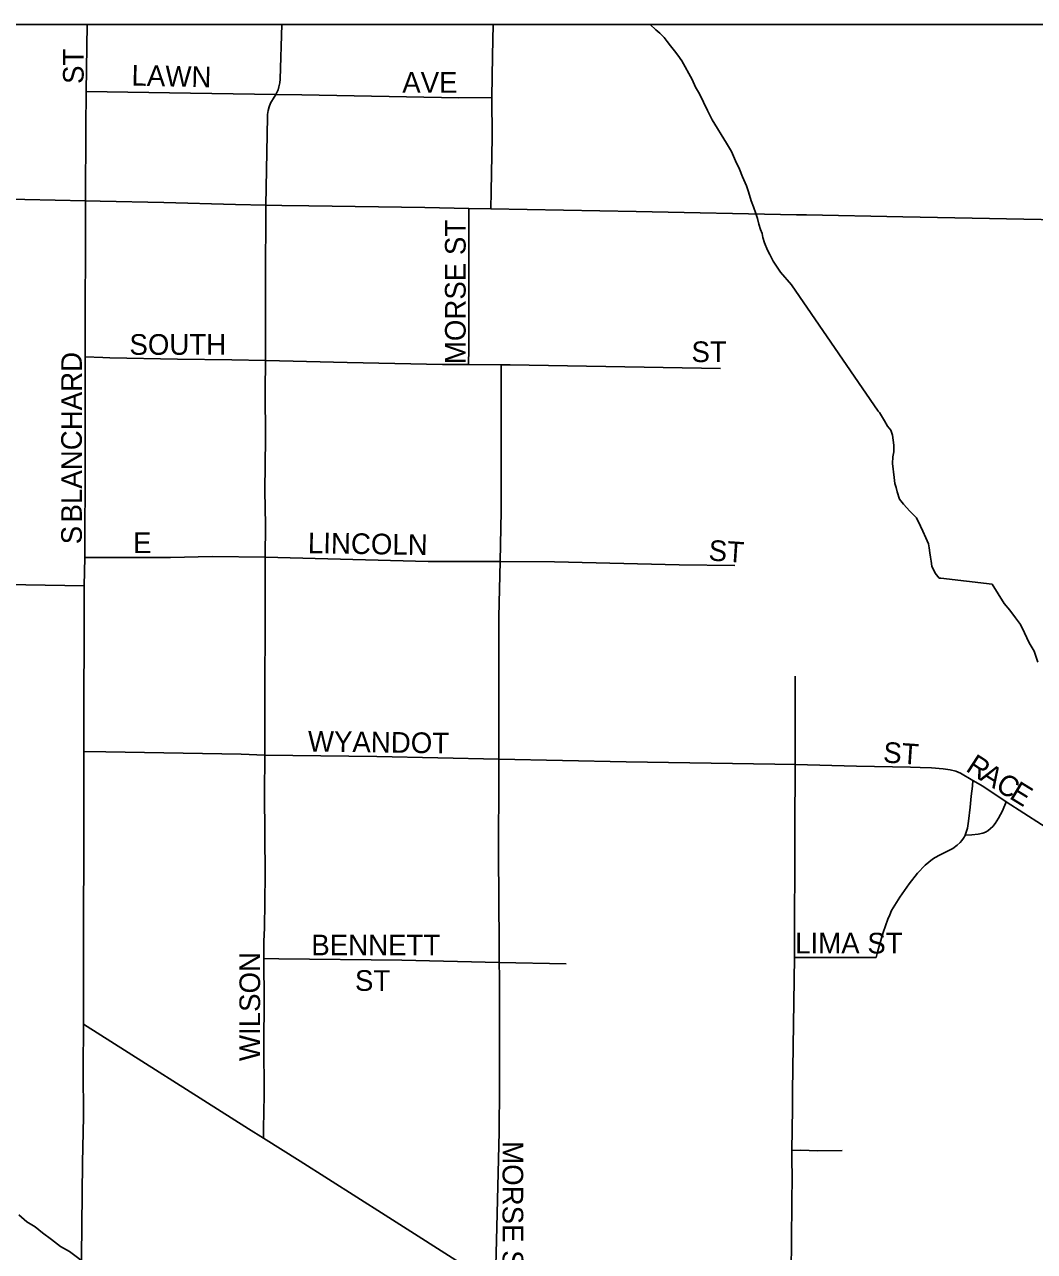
# Model space of a CAD drawing. Extents: x 0 to 68, y 0 to 52.9.
# Drawn here: x 54.894 to 56.116, y 51.458 to 52.941 of the extents above; entities that cross this region are included whole.
import ezdxf

# ---------------------------------------------------------------- set-up
doc = ezdxf.new("R2010")
doc.units = 0
for name, color, linetype in [('Default', 7, 'Continuous'), ('GM_X_Minor_River', 7, 'Continuous'), ('GM_X_State_Route', 7, 'Continuous')]:
    doc.layers.add(name, color=color, linetype=linetype)

msp = doc.modelspace()

# ---------------------------------------------------------------- linework, layer by layer
at = {"layer": 'Default'}
msp.add_line((49.5172, 52.9414), (67.9972, 52.9414), dxfattribs=at)
for points in [[(54.969, 52.8604), (54.9704, 52.9414)], [(55.1984, 52.857), (55.2011, 52.8624), (55.2022, 52.866), (55.2029, 52.8695), (55.2032, 52.871), (55.2037, 52.8752), (55.2055, 52.9414)], [(55.4597, 52.8532), (55.4606, 52.9035), (55.4612, 52.9414)], [(54.9682, 52.7284), (54.9685, 52.817), (54.969, 52.8604)], [(54.969, 52.8604), (55.0951, 52.8585), (55.1984, 52.857)], [(55.1864, 52.7231), (55.1884, 52.83), (55.1885, 52.8327), (55.1893, 52.8376), (55.1904, 52.8418), (55.1921, 52.8464), (55.1931, 52.8482), (55.1952, 52.8518), (55.1984, 52.857)], [(55.1984, 52.857), (55.2298, 52.8564), (55.4199, 52.8529), (55.4597, 52.8532)], [(55.4584, 52.7187), (55.4588, 52.7395), (55.4599, 52.8053), (55.4597, 52.8532)], [(54.9678, 52.5396), (54.9682, 52.7284)], [(55.1857, 52.5351), (55.1857, 52.6294), (55.1864, 52.7231)], [(55.4316, 52.5303), (55.4317, 52.5495), (55.432, 52.5984), (55.4317, 52.6296), (55.4318, 52.6868), (55.4318, 52.7104), (55.4318, 52.7192)], [(54.9672, 52.2969), (54.9676, 52.4171), (54.9678, 52.5396)], [(54.9678, 52.5396), (54.9892, 52.5387), (54.9975, 52.5383), (55.0796, 52.5367), (55.1453, 52.536), (55.1857, 52.5351)], [(55.1856, 52.2974), (55.1857, 52.3364), (55.1852, 52.3775), (55.1859, 52.441), (55.1856, 52.4985), (55.1857, 52.5351)], [(55.1857, 52.5351), (55.2027, 52.5347), (55.2848, 52.533), (55.3998, 52.5305), (55.4316, 52.5303)], [(55.4316, 52.5303), (55.471, 52.53)], [(55.4697, 52.2922), (55.471, 52.3532), (55.471, 52.511), (55.471, 52.53)], [(55.471, 52.53), (55.4818, 52.5299), (55.7361, 52.5257)], [(54.9665, 52.2629), (54.9672, 52.2969)], [(54.9672, 52.2969), (54.9896, 52.2969), (55.071, 52.2969), (55.1212, 52.2981), (55.1856, 52.2974)], [(55.1849, 52.0579), (55.1856, 52.2974)], [(55.1856, 52.2974), (55.3828, 52.2924), (55.4697, 52.2922)], [(55.4683, 52.0534), (55.4683, 52.2253), (55.4697, 52.2922)], [(55.4697, 52.2922), (55.5355, 52.292), (55.6862, 52.2883), (55.7537, 52.2873)], [(55.8267, 52.0466), (55.8267, 52.1536)], [(54.9661, 52.0625), (54.9927, 52.062), (55.1565, 52.0591), (55.1849, 52.0579)], [(55.184, 51.8122), (55.1838, 51.8333), (55.1848, 51.8488), (55.1853, 51.9132), (55.1846, 52.0115), (55.1849, 52.0579)], [(55.1849, 52.0579), (55.3204, 52.0565), (55.4683, 52.0534)], [(55.4684, 51.8072), (55.4686, 51.8286), (55.4677, 51.9389), (55.4681, 52.0345), (55.4683, 52.0534)], [(55.4683, 52.0534), (55.6223, 52.0501), (55.8019, 52.0473), (55.8267, 52.0466)], [(55.8258, 51.8136), (55.8262, 51.968), (55.8267, 52.0466)], [(55.8267, 52.0466), (55.9006, 52.0448), (55.9659, 52.0434), (55.9778, 52.0432), (55.9913, 52.0429), (56.0054, 52.0416), (56.0138, 52.0403), (56.0209, 52.0386), (56.0264, 52.0365)], [(56.0414, 52.0276), (56.0264, 52.0365)], [(56.0322, 51.9615), (56.0348, 51.97), (56.0363, 51.9782), (56.0382, 51.9951), (56.0395, 52.0086), (56.0411, 52.0207), (56.0414, 52.0276)], [(56.0817, 52.0018), (56.0534, 52.0206), (56.0414, 52.0276)], [(56.0322, 51.9615), (56.0403, 51.9617), (56.0479, 51.9627), (56.0536, 51.9638), (56.0567, 51.965), (56.0594, 51.9667), (56.0627, 51.9693), (56.0654, 51.9719), (56.0685, 51.9756), (56.0724, 51.9818), (56.0771, 51.9908), (56.0817, 52.0018)], [(56.2744, 51.8904), (56.2663, 51.8956), (56.243, 51.9076), (56.2012, 51.9304), (56.1666, 51.9493), (56.1243, 51.9744), (56.0817, 52.0018)], [(55.9243, 51.8133), (55.9264, 51.8216), (55.933, 51.8438), (55.9387, 51.8597), (55.9411, 51.8652), (55.9432, 51.8702), (55.9533, 51.8864), (55.9643, 51.9026), (55.9746, 51.9154), (55.9837, 51.9249), (55.9925, 51.9322), (55.996, 51.9345), (56.0009, 51.9373), (56.0171, 51.9454), (56.0225, 51.9491), (56.026, 51.9525), (56.0281, 51.955), (56.0301, 51.9576), (56.032, 51.9609), (56.0322, 51.9615)], [(55.1834, 51.5949), (55.1836, 51.6067), (55.1843, 51.647), (55.184, 51.7106), (55.1843, 51.7594), (55.184, 51.8122)], [(55.184, 51.8122), (55.2019, 51.812), (55.3507, 51.8104), (55.4684, 51.8072)], [(55.4592, 51.4207), (55.4617, 51.4274), (55.4645, 51.4368), (55.4646, 51.4412), (55.4653, 51.4713), (55.4673, 51.5529), (55.4684, 51.6027), (55.4688, 51.6567), (55.4691, 51.7898), (55.4684, 51.8072)], [(55.4684, 51.8072), (55.5496, 51.8059)], [(55.8224, 51.5801), (55.8231, 51.6307), (55.8233, 51.6518), (55.8258, 51.8136)], [(55.8258, 51.8136), (55.8423, 51.8136), (55.8678, 51.8136), (55.9243, 51.8133)], [(54.9604, 51.0568), (54.9605, 51.0661), (54.9609, 51.1564), (54.962, 51.2301), (54.9622, 51.3367), (54.9633, 51.4515), (54.9647, 51.5657), (54.9656, 51.6207), (54.9653, 51.6782), (54.9659, 51.7329)], [(55.8211, 51.1945), (55.8212, 51.2131), (55.8212, 51.2196), (55.8212, 51.2842), (55.8212, 51.3087), (55.8217, 51.4297), (55.8219, 51.4751), (55.8229, 51.5522), (55.8225, 51.5646), (55.8224, 51.5801)], [(55.8224, 51.5801), (55.8328, 51.5804), (55.8538, 51.5798), (55.8833, 51.5799)]]:
    msp.add_lwpolyline(points, dxfattribs=at)
at = {"layer": 'GM_X_Minor_River'}
for points in [[(55.651, 52.9414), (55.6512, 52.9413), (55.6581, 52.9351), (55.663, 52.931), (55.6679, 52.9259), (55.6718, 52.9208), (55.6757, 52.9157), (55.6806, 52.9096), (55.6845, 52.9045), (55.6894, 52.8974), (55.6933, 52.8903), (55.6981, 52.8821), (55.702, 52.8751), (55.7058, 52.8659), (55.7107, 52.8578), (55.7155, 52.8477), (55.7203, 52.8376), (55.7261, 52.8264), (55.7436, 52.798), (55.7494, 52.7878), (55.7542, 52.7767), (55.759, 52.7666), (55.7628, 52.7575), (55.7676, 52.7463), (55.7695, 52.7403), (55.7714, 52.7352), (55.7733, 52.7282), (55.7761, 52.7211), (55.779, 52.713), (55.7809, 52.707), (55.7827, 52.6999), (55.7846, 52.6938), (55.7865, 52.6888), (55.7874, 52.6838)], [(55.7874, 52.6838), (55.7893, 52.6777), (55.7931, 52.6686), (55.796, 52.6635), (55.7999, 52.6554), (55.8038, 52.6493), (55.8086, 52.6422), (55.8219, 52.6267)], [(55.8219, 52.6267), (55.9268, 52.4741)], [(55.9268, 52.4741), (55.9286, 52.4723), (55.9344, 52.4621), (55.9383, 52.456), (55.9422, 52.4509), (55.9441, 52.4449), (55.945, 52.4389), (55.9459, 52.4328), (55.9457, 52.4248), (55.9446, 52.4188), (55.9444, 52.4108), (55.9461, 52.3937), (55.9469, 52.3867), (55.9488, 52.3816), (55.9497, 52.3766), (55.9526, 52.3675), (55.9575, 52.3614), (55.9653, 52.3532), (55.9732, 52.345), (55.978, 52.3349), (55.9809, 52.3288), (55.9847, 52.3207), (55.9876, 52.3136), (55.9885, 52.3086), (55.9894, 52.3026), (55.9903, 52.2975), (55.9912, 52.2925), (55.992, 52.2864), (55.9959, 52.2783), (56.0008, 52.2722), (56.0028, 52.2722), (56.0649, 52.2649)], [(56.0649, 52.2649), (56.0794, 52.2416), (56.0863, 52.2334), (56.0931, 52.2242), (56.099, 52.2161), (56.1038, 52.206), (56.1096, 52.1938), (56.1154, 52.1837), (56.1201, 52.1705)], [(54.8875, 51.5023), (54.8974, 51.494), (54.9073, 51.4878), (54.9162, 51.4806), (54.9271, 51.4724), (54.9379, 51.4641), (54.9488, 51.4579), (54.9587, 51.4507), (54.9696, 51.4424), (54.9864, 51.4311), (54.9973, 51.4228), (55.0081, 51.4136), (55.021, 51.4053), (55.0319, 51.398)]]:
    msp.add_lwpolyline(points, dxfattribs=at)
at = {"layer": 'GM_X_State_Route'}
for points in [[(54.1957, 52.764), (54.2546, 52.7624), (54.3149, 52.7606), (54.4211, 52.7574), (54.5313, 52.7516), (54.5598, 52.7502), (54.6658, 52.7432), (54.7391, 52.7371), (54.7881, 52.733), (54.8209, 52.7316), (54.9682, 52.7284), (54.9859, 52.728), (55.0628, 52.7261)], [(55.0628, 52.7261), (55.1497, 52.7239), (55.1864, 52.7231), (55.2056, 52.7228), (55.2385, 52.7221), (55.3787, 52.7202), (55.4318, 52.7192)], [(55.4318, 52.7192), (55.4584, 52.7187), (55.6343, 52.7154), (55.8281, 52.7115)], [(55.8281, 52.7115), (55.8404, 52.7113), (55.9568, 52.709), (56.1871, 52.7045)], [(53.7152, 52.2901), (53.7658, 52.2895), (53.8887, 52.2868), (53.9566, 52.2852), (54.118, 52.2812), (54.188, 52.2792), (54.2323, 52.277), (54.527, 52.2701), (54.6172, 52.2679), (54.7073, 52.2673), (54.9665, 52.2629)], [(54.9665, 52.2629), (54.9661, 52.0625), (54.9659, 51.7381)], [(54.9659, 51.7381), (54.9659, 51.7329), (55.1653, 51.6062), (55.1834, 51.5949), (55.2278, 51.5671), (55.3305, 51.5019), (55.4339, 51.4362)]]:
    msp.add_lwpolyline(points, dxfattribs=at)

# ---------------------------------------------------------------- texts
at = {"layer": 'Default'}
for s, rotation, p in [('ST', 90, (54.966, 52.8696)), ('LAWN', 358.6368, (55.0236, 52.8677)), ('AVE', 0, (55.3513, 52.8589)), ('MORSE ST', 90, (55.428, 52.5308)), ('SOUTH', 0, (55.0213, 52.5421)), ('ST', 0, (55.7011, 52.5333)), ('BLANCHARD', 90, (54.9638, 52.3394)), ('S', 90, (54.9638, 52.313)), ('E', 0, (55.0257, 52.3023)), ('LINCOLN', 359.0613, (55.237, 52.3023)), ('ST', 356.1879, (55.7212, 52.2935)), ('WYANDOT', 359.2047, (55.237, 52.0625)), ('ST', 356.1879, (55.9324, 52.0493)), ('R', 326.97, (56.0316, 52.0397)), ('A', 328.1913, (56.0487, 52.0286)), ('C', 328.3944, (56.0674, 52.0169)), ('E', 328.3974, (56.0843, 52.0065)), ('BENNETT', 0, (55.2413, 51.8161)), ('LIMA ST', 0, (55.8265, 51.8183)), ('WILSON', 90, (55.1794, 51.6882)), ('ST', 0, (55.2941, 51.7731)), ('MORSE ST', 270, (55.4726, 51.5914))]:
    msp.add_text(s, height=0.025, rotation=rotation, dxfattribs=at).set_placement(p)

doc.saveas('drawing.dxf')
